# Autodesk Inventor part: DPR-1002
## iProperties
Created: 2004-11
Part Number: DPR-1002
Cost Center: 0 lbmass
Document SubType Name: Modeling
Designer: busseym
Manufacturer: Standard
Standards Organization: Custom
Stock Number: DPR-1002
Density: 1 g/cm^3
CAGE: 1LJX3
Dept. ID: Product Design
Description #2: ---
Finish #1: ---
Finish #2: ---
Material ID: ---
Project Number: ---
Author: busseym
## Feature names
1. Extrusion1
2. Extrusion2
3. Fillet1
4. Extrusion3
5. Mirror1
6. Extrusion4
7. Mirror2
8. Mirror3
